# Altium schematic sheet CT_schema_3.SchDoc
size 552 x 434 mm
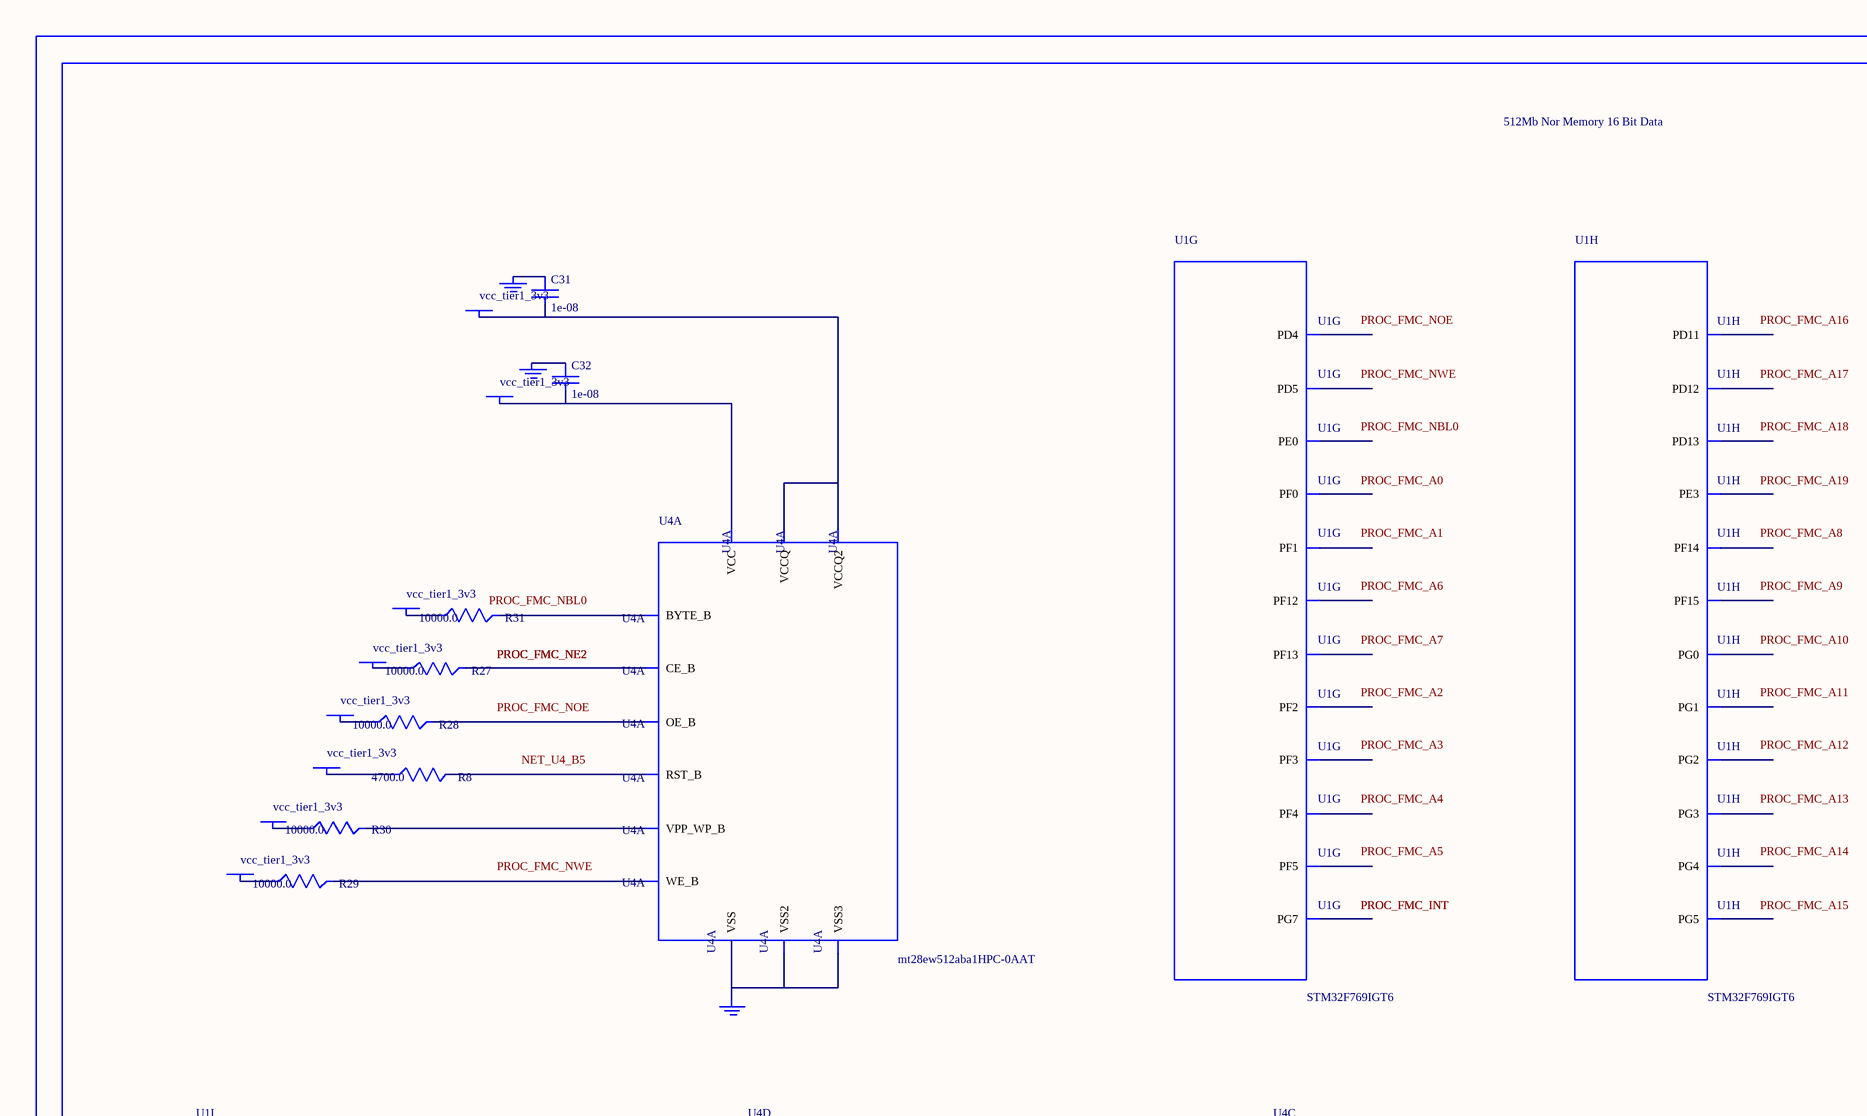
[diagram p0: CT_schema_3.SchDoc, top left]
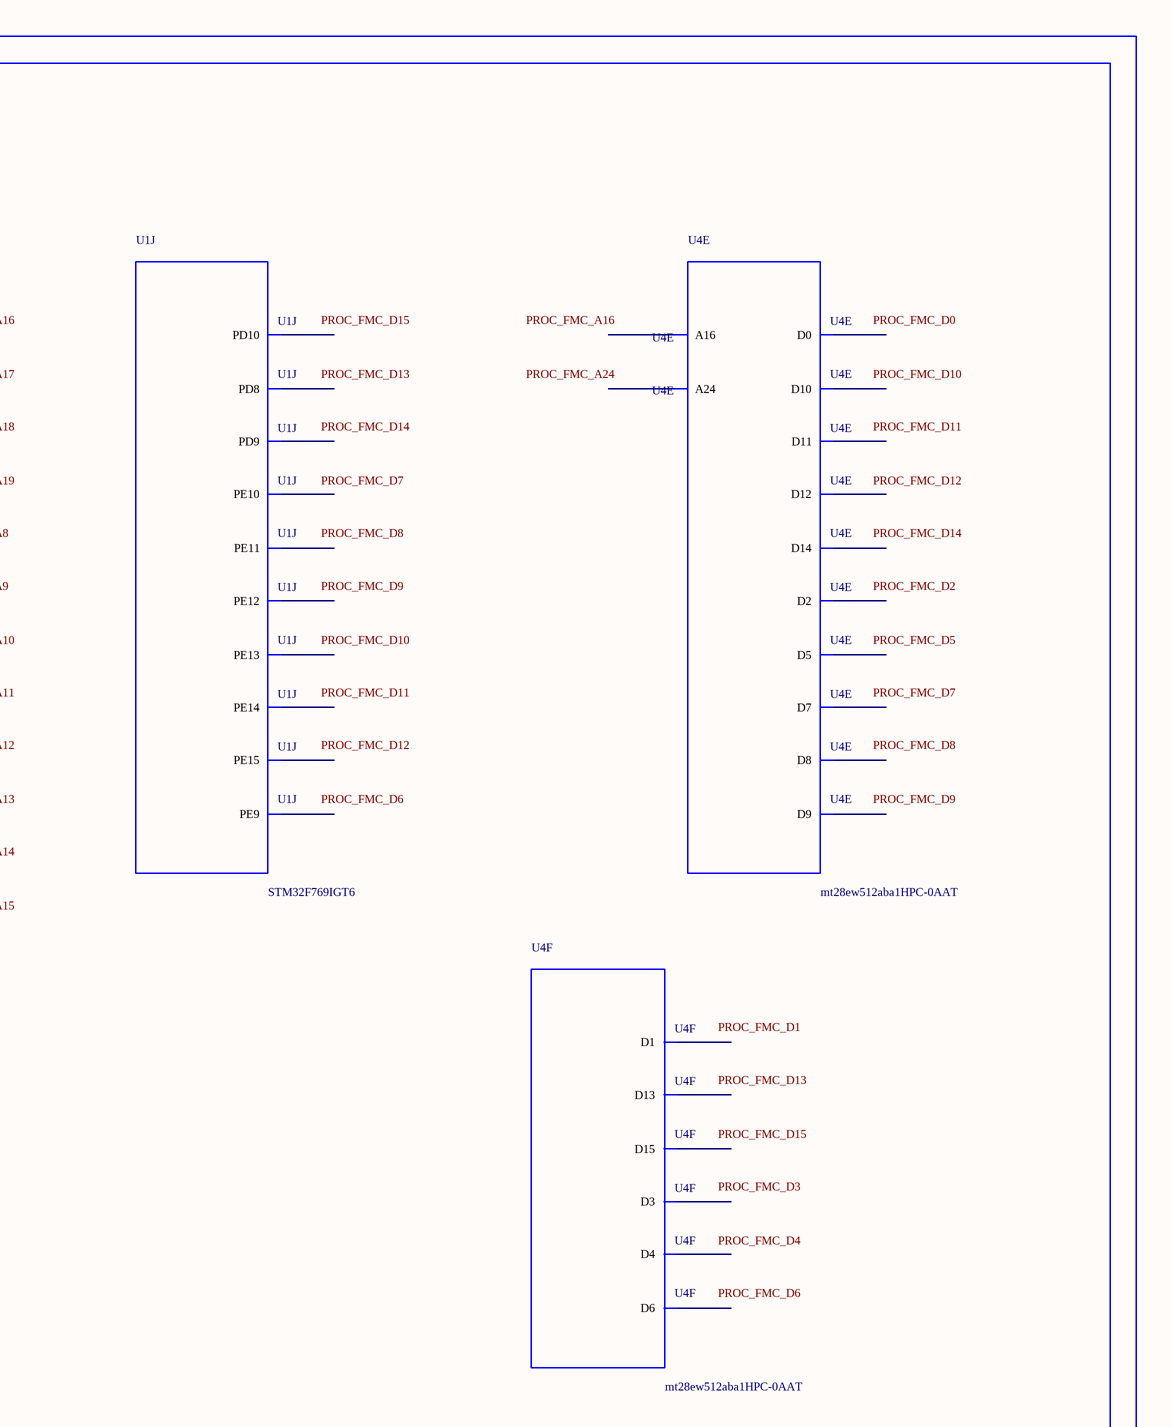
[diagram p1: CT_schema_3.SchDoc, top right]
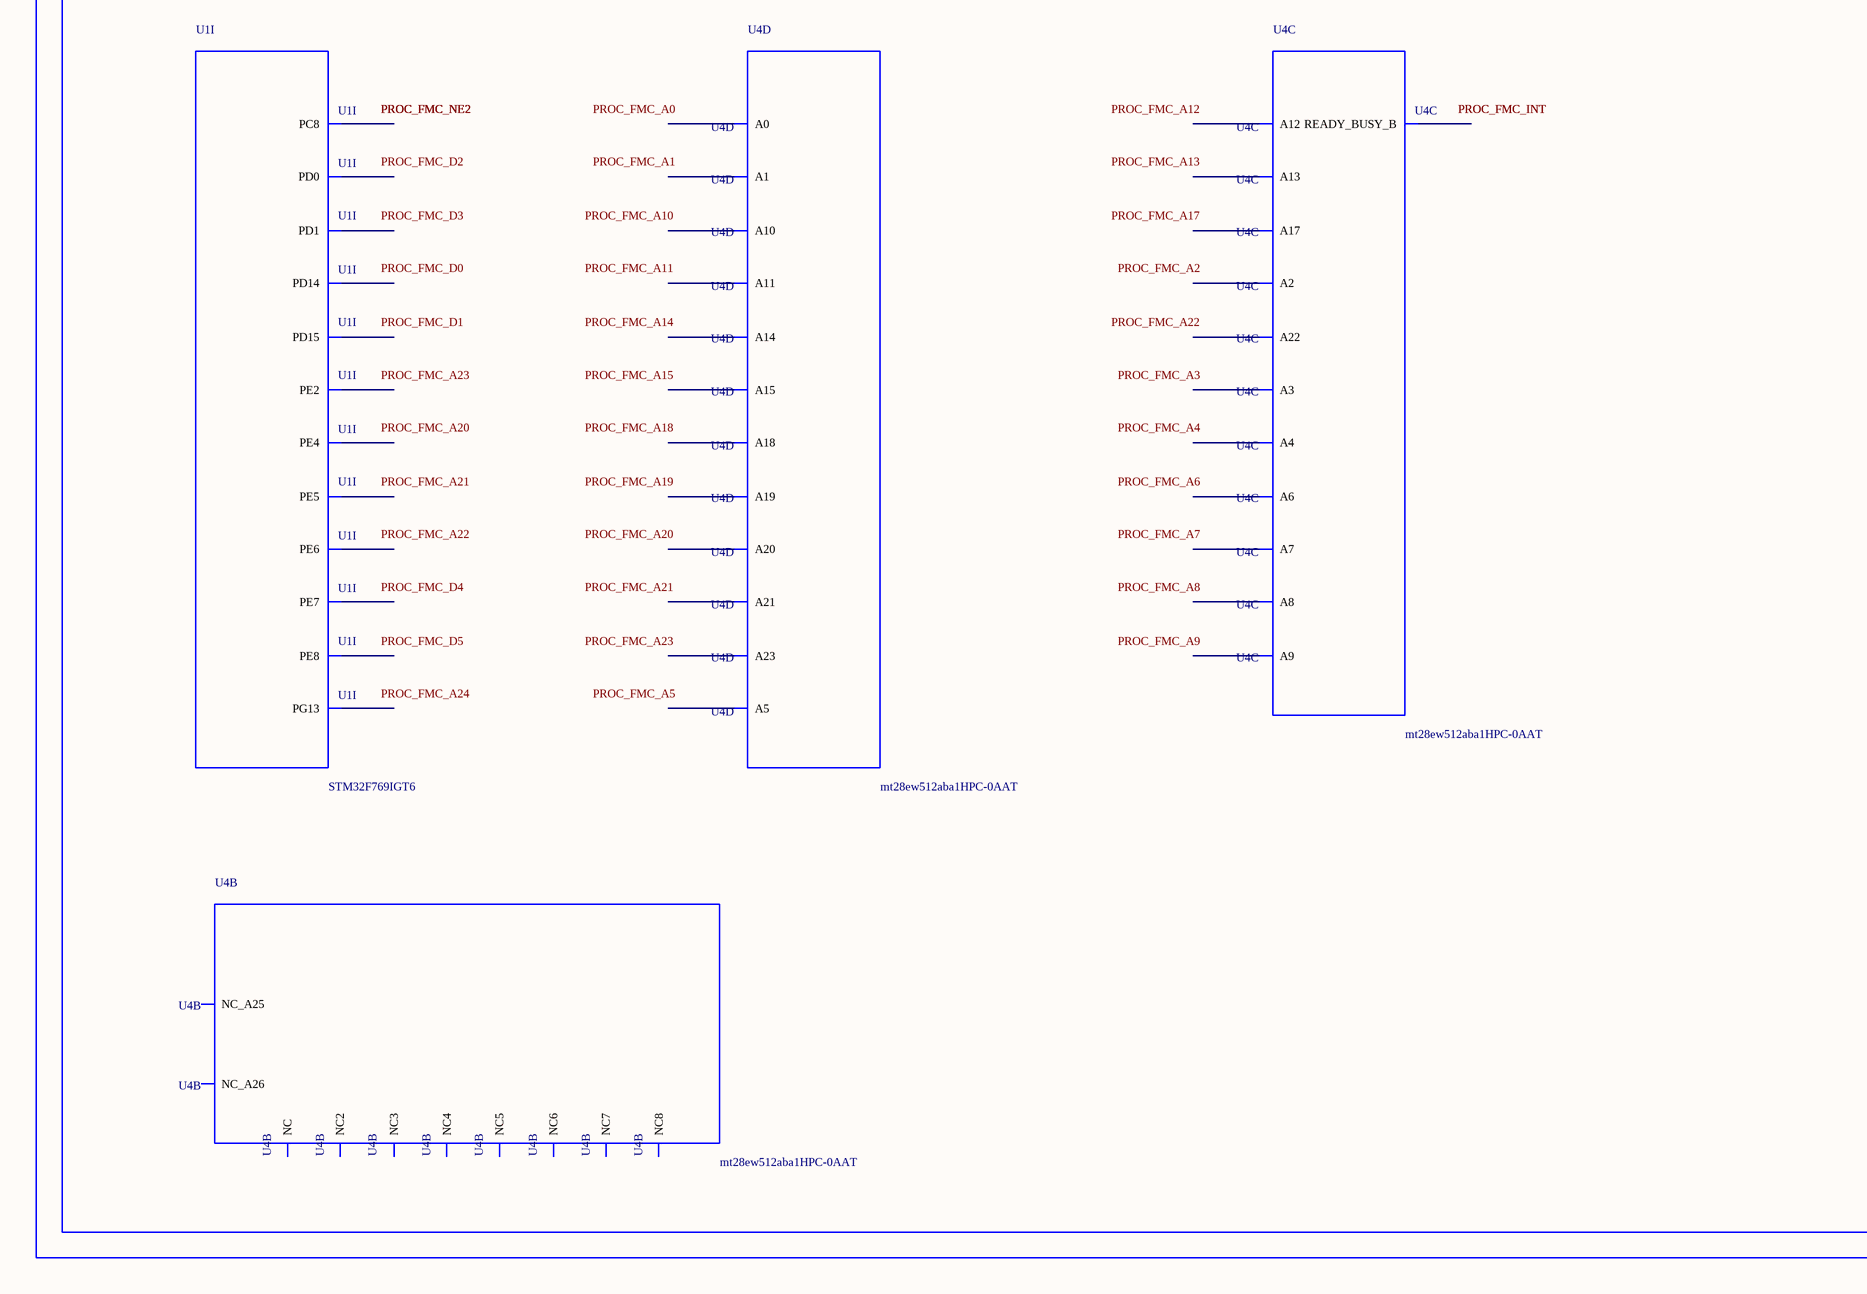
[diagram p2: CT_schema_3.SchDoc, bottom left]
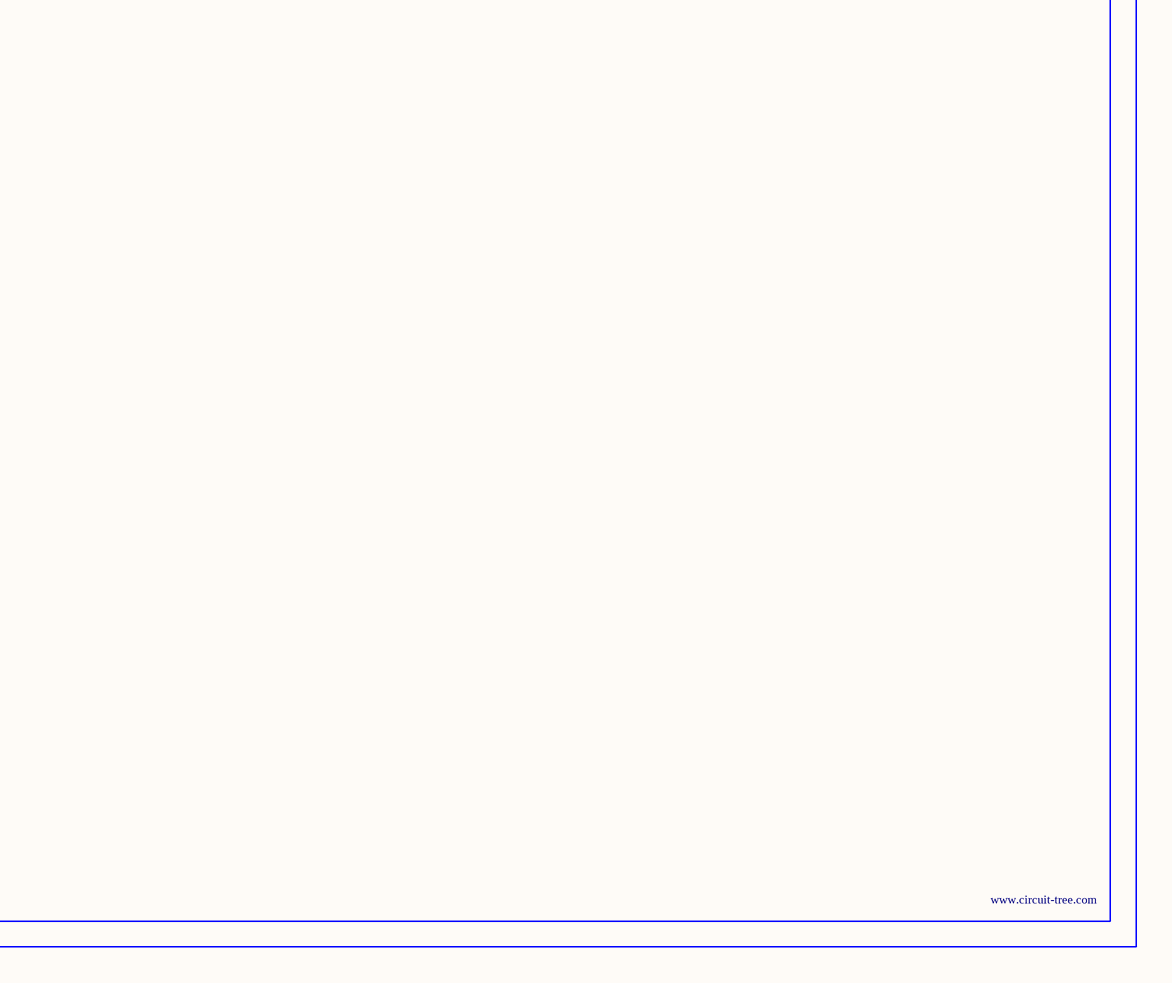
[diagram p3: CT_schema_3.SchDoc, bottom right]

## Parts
BORDER2  (no value)
C31  1e-08  [C0402]
C32  1e-08  [C0402]
GND_INSTANCE_2_0  (no value)
GND_INSTANCE_2_1  (no value)
GND_INSTANCE_2_2  (no value)
POWER_INSTANCE_2_0  vcc_tier1_3v3
POWER_INSTANCE_2_1  vcc_tier1_3v3
POWER_INSTANCE_2_2  vcc_tier1_3v3
POWER_INSTANCE_2_3  vcc_tier1_3v3
POWER_INSTANCE_2_4  vcc_tier1_3v3
POWER_INSTANCE_2_5  vcc_tier1_3v3
POWER_INSTANCE_2_6  vcc_tier1_3v3
POWER_INSTANCE_2_7  vcc_tier1_3v3
R8  4700.0  [R0603]
R27  10000.0  [R0603]
R28  10000.0  [R0603]
R29  10000.0  [R0603]
R30  10000.0  [R0603]
R31  10000.0  [R0603]
U1  STM32F769IGT6  [LQFP176]  (parts G,H,I,J of 13)
U4  mt28ew512aba1HPC-0AAT  [LBGA-64]  (parts A,B,C,D,E,F of 6)

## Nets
NetC31_1: C31.1 GND_INSTANCE_2_0.0(GND)
NetC31_2: C31.2 POWER_INSTANCE_2_0.0(PWR) U4.D8(VCCQ) U4.F1(VCCQ2)
NetC32_1: C32.1 GND_INSTANCE_2_1.0(GND)
NetC32_2: C32.2 POWER_INSTANCE_2_1.0(PWR) U4.G5(VCC)
NetGND_INSTANCE_2_2_0: GND_INSTANCE_2_2.0(GND) U4.E8(VSS) U4.H2(VSS2) U4.H7(VSS3)
NetPOWER_INSTANCE_2_2_0: POWER_INSTANCE_2_2.0(PWR) R27.1
NetPOWER_INSTANCE_2_3_0: POWER_INSTANCE_2_3.0(PWR) R28.1
NetPOWER_INSTANCE_2_4_0: POWER_INSTANCE_2_4.0(PWR) R29.1
NetPOWER_INSTANCE_2_5_0: POWER_INSTANCE_2_5.0(PWR) R30.1
NetPOWER_INSTANCE_2_6_0: POWER_INSTANCE_2_6.0(PWR) R31.1
NetPOWER_INSTANCE_2_7_0: POWER_INSTANCE_2_7.0(PWR) R8.1
NetR8_2: R8.2 U4.B5(RST_B)
NetR27_2: R27.2 U4.F2(CE_B)
NetR28_2: R28.2 U4.G2(OE_B)
NetR29_2: R29.2 U4.A5(WE_B)
NetR30_2: R30.2 U4.B4(VPP_WP_B)
NetR31_2: R31.2 U4.F7(BYTE_B)

Not connected (* = marked no-connect by the designer): U1 1(PE2) 2(PE3) 3(PE4) 4(PE5) 5(PE6) 16(PF0) 17(PF1) 18(PF2) 19(PF3) 20(PF4) 21(PF5) 60(PF12) 63(PF13) 64(PF14) 65(PF15) 66(PG0) 67(PG1) 68(PE7) 69(PE8) 70(PE9) 73(PE10) 74(PE11) 75(PE12) 76(PE13) 77(PE14) 78(PE15) 89(PD8) 90(PD9) 91(PD10) 92(PD11) 93(PD12) 94(PD13) 97(PD14) 98(PD15) 110(PG2) 111(PG3) 112(PG4) 113(PG5) 115(PG7) 121(PC8) 142(PD0) 143(PD1) 146(PD4) 147(PD5) 156(PG13) 169(PE0); U4 A1(NC) A2(A3) A3(A7) A4(READY_BUSY_B) A6(A9) A7(A13) A8(NC2) B1(NC_A26) B2(A4) B3(A17) B6(A8) B7(A12) B8(A22) C1(NC3) C2(A2) C3(A6) C4(A18) C5(A21) C6(A10) C7(A14) C8(A23) D1(NC4) D2(A1) D3(A5) D4(A20) D5(A19) D6(A11) D7(A15) E1(NC5) E2(A0) E3(D0) E4(D2) E5(D5) E6(D7) E7(A16) F3(D8) F4(D10) F5(D12) F6(D14) F8(A24) G1(NC6) G3(D9) G4(D11) G6(D13) G7(D15) G8(NC_A25) H1(NC7) H3(D1) H4(D3) H5(D4) H6(D6) H8(NC8)

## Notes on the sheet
- Labels drawn without touching a wire or pin: NET_U4_B5, PROC_FMC_A0, PROC_FMC_A1, PROC_FMC_A2, PROC_FMC_A3, PROC_FMC_A4, PROC_FMC_A5, PROC_FMC_A6, PROC_FMC_A7, PROC_FMC_A8, PROC_FMC_A9, PROC_FMC_A10, PROC_FMC_A11, PROC_FMC_A12, PROC_FMC_A13, PROC_FMC_A14, PROC_FMC_A15, PROC_FMC_A16, PROC_FMC_A17, PROC_FMC_A18, PROC_FMC_A19, PROC_FMC_A20, PROC_FMC_A21, PROC_FMC_A22, PROC_FMC_A23, PROC_FMC_A24, PROC_FMC_D0, PROC_FMC_D1, PROC_FMC_D2, PROC_FMC_D3, PROC_FMC_D4, PROC_FMC_D5, PROC_FMC_D6, PROC_FMC_D7, PROC_FMC_D8, PROC_FMC_D9, PROC_FMC_D10, PROC_FMC_D11, PROC_FMC_D12, PROC_FMC_D13, PROC_FMC_D14, PROC_FMC_D15, PROC_FMC_NBL0, PROC_FMC_NOE, PROC_FMC_NWE

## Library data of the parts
BORDER2 = BORDER_PAGE2
C31 C32 = C0402C103K3RAC
GND_INSTANCE_2_0-GND_INSTANCE_2_2 = GND
POWER_INSTANCE_2_0-POWER_INSTANCE_2_7 = PWR
R8 = RC0603JR-074K7L
R27-R31 = RC0603JR-0710KL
